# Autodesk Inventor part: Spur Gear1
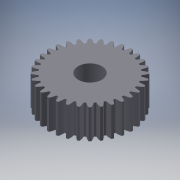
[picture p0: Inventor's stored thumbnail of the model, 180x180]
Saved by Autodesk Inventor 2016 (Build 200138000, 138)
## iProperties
Created: 2016-10
Part Number: Spur Gear1
Material: Steel
Document SubType Name: Modeling
Designer: Ingenieria
Categories: <?xml version="1.0" encoding="UTF-16"?> <MemberInstance><Categories><FamilyTemplate><FamilyTemplateParameter ValueType="xs:double" Id="1" ObjectReferenceKey="da
Density: 1 g/cm^3
Appearance: Steel
CustomPartVersion: 1
Author: Ingenieria
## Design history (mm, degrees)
sketch "Sketch1"
  geometry: C1 r 85.347 at (0, 0)
  constraints: 1 centre point
  dimensions: "d0" = 170.69345 diameter of C1 (= da_da)
extrude "Extrusion1" new body sketch "Sketch1" distance "d1" = 60 (= da_b); taper "d2" = 0 deg
workplane "Work Plane2"
sketch "Sketch2"
  geometry: C1 r 85.347 at (0, 0) reference; C2 r 80.367 at (0, 0)
  constraints: 1 centre point, 1 coincident
  dimensions: "d3" = 160.73412 diameter of C2 (= da_dw)
feature "Pitch Diameter" sketch "Sketch2" dims "d4" = 10, "d5" = 0
workplane "Work Plane8"
workplane "Work Plane9"
feature "Spur Gear" dims "d4" = 10, "da_b" = 60, "da_d" = 160, "da_aw" = 341.56, "da_da" = 170.69345, "da_df" = 148.24663, "da_dw" = 160.73412, angle "da_beta" = 0 deg, "da_lefttooth" = 0, "da_righttooth" = 0
sketch "Sketch3"
  geometry: C1 r 24 at (0, 0); 1 further point
  constraints: 1 centre point, 1 coincident
  dimensions: "d49" = 48 diameter of C1
extrude "Extrusion2" cut sketch "Sketch3" stored distance "d50" = 10; taper "d51" = 0 deg
body "Solid1"
body "Srf1"
other parameters: "d16" = 341.56 (= da_aw), "d17" = 0, "d34" = 0.98175 (computed from da_z), "d39" = 0, "d41" = 0, "d43" = 341.56 (= da_aw), "d46" = 341.56 (= da_aw), "d47" = 0, "d48" = 0
